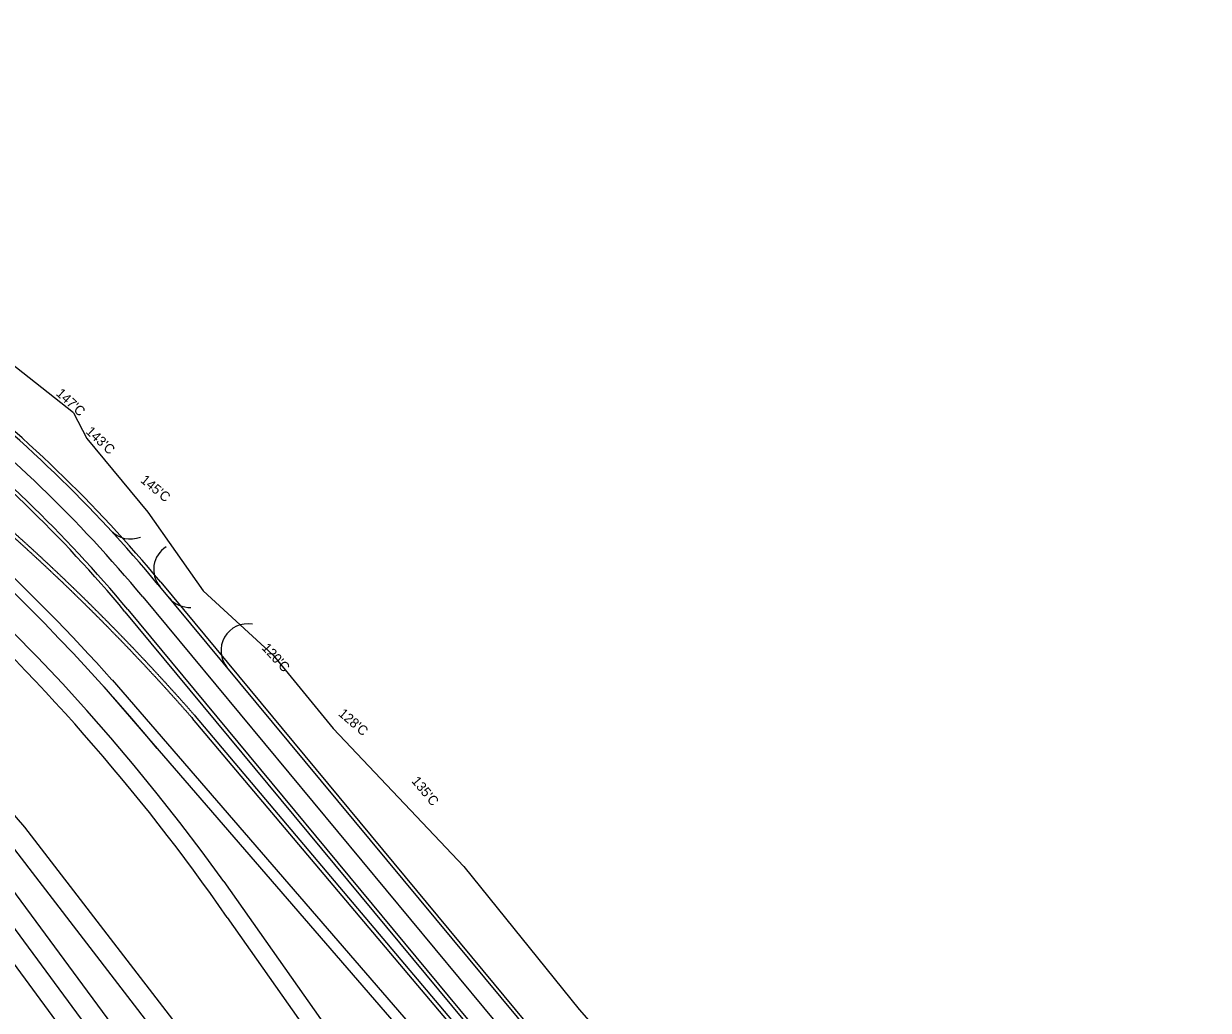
# Model space of a CAD drawing. Extents: x 1942118 to 1978871, y 789467 to 829913.
# Drawn here: x 1970305 to 1970967, y 797225 to 797777 of the extents above; entities that cross this region are included whole.
import ezdxf

# ---------------------------------------------------------------- set-up
doc = ezdxf.new("R2010")
doc.units = 0
for name, color, linetype in [('RD_PD_ALT1_CL', 7, 'Continuous'), ('RD_PD_ALT1_TrvlWay', 7, 'Continuous'), ('RD_PD_CstnLmt', 7, 'Continuous'), ('RD_PD_Driveway', 7, 'Continuous'), ('RD_PD_Final_LnLine', 7, 'Continuous'), ('RD_PD_Final_TrvlWay', 7, 'Continuous'), ('RD_PD_PaintMed', 7, 'Continuous'), ('RD_PD_PaveShd', 7, 'Continuous'), ('RD_PD_TX_CstnLmt', 7, 'Continuous'), ('RD_PD_WallFill', 7, 'Continuous')]:
    doc.layers.add(name, color=color, linetype=linetype)

msp = doc.modelspace()

# ---------------------------------------------------------------- linework, layer by layer
at = {"layer": 'RD_PD_ALT1_CL'}
msp.add_line((1970416.68, 797296.78), (1970931.78, 796566.41), dxfattribs=at)
at = {"layer": 'RD_PD_ALT1_TrvlWay'}
for radius, start, end in [(1150, 35.62905, 163.61097), (1166, 39.67545, 76.52951)]:
    msp.add_arc((1969481.96, 796626.87), radius, start, end, dxfattribs=at)
at = {"layer": 'RD_PD_CstnLmt'}
for p, q in [((1970332.67, 797559.08), (1970288.61, 797593.77)), ((1970332.67, 797559.08), (1970340.14, 797544.71)), ((1970340.14, 797544.71), (1970374.27, 797503.41)), ((1970374.27, 797503.41), (1970405.24, 797459.44)), ((1970405.24, 797459.44), (1970444.36, 797423.54)), ((1970444.36, 797423.54), (1970477.86, 797382.4)), ((1970477.86, 797382.4), (1970550.94, 797305.27)), ((1970550.94, 797305.27), (1970615.52, 797225.13)), ((1970615.52, 797225.13), (1970682.04, 797150.08))]:
    msp.add_line(p, q, dxfattribs=at)
at = {"layer": 'RD_PD_Driveway'}
for centre, start, end in [((1970364.49, 797503.48), 222.69654, 291.77483), ((1970392.48, 797471.42), 122.63026, 219.55353), ((1970397.66, 797465.18), 219.67545, 272.49926), ((1970430.13, 797426.03), 80.09893, 219.67545)]:
    msp.add_arc(centre, 15, start, end, dxfattribs=at)
at = {"layer": 'RD_PD_Final_LnLine'}
for p, q in [((1970284.69, 797310.85), (1970423.91, 797122.01)), ((1970275.06, 797303.7), (1970437.07, 797083.94)), ((1970265.4, 797296.58), (1970516.36, 796956.16))]:
    msp.add_line(p, q, dxfattribs=at)
at = {"layer": 'RD_PD_Final_TrvlWay'}
for p, q in [((1970379.89, 797463.11), (1970878.63, 796861.84)), ((1970362.95, 797449.06), (1970861.7, 796847.8)), ((1970349.66, 797405.75), (1970962.87, 796696.8)), ((1970468.57, 797095.3), (1970296.15, 797319.65))]:
    msp.add_line(p, q, dxfattribs=at)
for radius in [761, 739]:
    msp.add_arc((1969794.16, 796977.26), radius, 39.67545, 52.49072, dxfattribs=at)
at = {"layer": 'RD_PD_PaintMed'}
msp.add_line((1970371.42, 797456.09), (1970870.17, 796854.82), dxfattribs=at)
msp.add_arc((1969794.16, 796977.26), 750, 39.67545, 52.49072, dxfattribs=at)
at = {"layer": 'RD_PD_PaveShd'}
for p, q in [((1970305.44, 797327.25), (1970063.47, 797605.51)), ((1970381.42, 797464.39), (1970880.17, 796863.12)), ((1970361.41, 797447.79), (1970860.16, 796846.52)), ((1970354.19, 797409.67), (1970967.4, 796700.73)), ((1970496.9, 797078.14), (1970305.44, 797327.25)), ((1970418.57, 797276.75), (1970626.31, 796982.2))]:
    msp.add_line(p, q, dxfattribs=at)
for centre, radius, start, end in [((1969481.96, 796626.87), 1172, 41.91244, 62.0768), ((1969794.16, 796977.26), 763, 39.67545, 52.49072), ((1969794.16, 796977.26), 737, 39.67545, 52.49072), ((1969481.96, 796626.87), 1140, 34.75543, 47.7995)]:
    msp.add_arc(centre, radius, start, end, dxfattribs=at)
at = {"layer": 'RD_PD_WallFill'}
for p, q in [((1970626.99, 797118.22), (1970399.23, 797388.09)), ((1970400.74, 797389.41), (1970628.53, 797119.5))]:
    msp.add_line(p, q, dxfattribs=at)
for radius in [8428, 8430]:
    msp.add_arc((1963181.81, 792525.99), radius, 31.397656, 33.979468, dxfattribs=at)
for points in [[(1970292.6, 797498.04), (1970293.12, 797497.59), (1970293.63, 797497.13), (1970294.15, 797496.68), (1970294.66, 797496.22), (1970295.18, 797495.76), (1970295.7, 797495.3), (1970296.21, 797494.84), (1970296.73, 797494.38), (1970297.24, 797493.92), (1970297.76, 797493.47), (1970298.27, 797493.01), (1970298.78, 797492.55), (1970299.3, 797492.09), (1970299.81, 797491.62), (1970300.33, 797491.16), (1970300.84, 797490.7), (1970301.35, 797490.24), (1970301.86, 797489.78), (1970302.38, 797489.32), (1970302.89, 797488.85), (1970303.4, 797488.39), (1970303.91, 797487.93), (1970304.42, 797487.46), (1970304.93, 797487), (1970305.45, 797486.54), (1970305.96, 797486.07), (1970306.47, 797485.61), (1970306.98, 797485.14), (1970307.49, 797484.68), (1970307.99, 797484.21), (1970308.5, 797483.75), (1970309.01, 797483.28), (1970309.52, 797482.81), (1970310.03, 797482.35), (1970310.54, 797481.88), (1970311.05, 797481.41), (1970311.55, 797480.94), (1970312.06, 797480.48), (1970312.57, 797480.01), (1970313.08, 797479.54), (1970313.58, 797479.07), (1970314.09, 797478.6), (1970314.59, 797478.13), (1970315.1, 797477.66), (1970315.61, 797477.19), (1970316.11, 797476.72), (1970316.62, 797476.25), (1970317.12, 797475.78), (1970317.62, 797475.31), (1970318.13, 797474.84), (1970318.63, 797474.37), (1970319.14, 797473.89), (1970319.64, 797473.42), (1970320.14, 797472.95), (1970320.65, 797472.48), (1970321.15, 797472), (1970321.65, 797471.53), (1970322.15, 797471.05), (1970322.65, 797470.58), (1970323.16, 797470.11), (1970323.66, 797469.63), (1970324.16, 797469.16), (1970324.66, 797468.68), (1970325.16, 797468.2), (1970325.66, 797467.73), (1970326.16, 797467.25), (1970326.66, 797466.78), (1970327.16, 797466.3), (1970327.66, 797465.82), (1970328.16, 797465.34), (1970328.65, 797464.87), (1970329.15, 797464.39), (1970329.65, 797463.91), (1970330.15, 797463.43)], [(1970291.28, 797496.55), (1970291.79, 797496.09), (1970292.31, 797495.63), (1970292.82, 797495.18), (1970293.34, 797494.72), (1970293.85, 797494.26), (1970294.37, 797493.81), (1970294.88, 797493.35), (1970295.4, 797492.89), (1970295.91, 797492.43), (1970296.42, 797491.97), (1970296.94, 797491.51), (1970297.45, 797491.06), (1970297.96, 797490.6), (1970298.48, 797490.14), (1970298.99, 797489.68), (1970299.5, 797489.22), (1970300.01, 797488.75), (1970300.52, 797488.29), (1970301.04, 797487.83), (1970301.55, 797487.37), (1970302.06, 797486.91), (1970302.57, 797486.45), (1970303.08, 797485.98), (1970303.59, 797485.52), (1970304.1, 797485.06), (1970304.61, 797484.59), (1970305.12, 797484.13), (1970305.63, 797483.67), (1970306.14, 797483.2), (1970306.65, 797482.74), (1970307.15, 797482.27), (1970307.66, 797481.81), (1970308.17, 797481.34), (1970308.68, 797480.87), (1970309.18, 797480.41), (1970309.69, 797479.94), (1970310.2, 797479.47), (1970310.7, 797479.01), (1970311.21, 797478.54), (1970311.72, 797478.07), (1970312.22, 797477.6), (1970312.73, 797477.14), (1970313.23, 797476.67), (1970313.74, 797476.2), (1970314.24, 797475.73), (1970314.75, 797475.26), (1970315.25, 797474.79), (1970315.76, 797474.32), (1970316.26, 797473.85), (1970316.76, 797473.38), (1970317.27, 797472.91), (1970317.77, 797472.43), (1970318.27, 797471.96), (1970318.77, 797471.49), (1970319.27, 797471.02), (1970319.78, 797470.55), (1970320.28, 797470.07), (1970320.78, 797469.6), (1970321.28, 797469.13), (1970321.78, 797468.65), (1970322.28, 797468.18), (1970322.78, 797467.7), (1970323.28, 797467.23), (1970323.78, 797466.76), (1970324.28, 797466.28), (1970324.78, 797465.8), (1970325.28, 797465.33), (1970325.78, 797464.85), (1970326.27, 797464.38), (1970326.77, 797463.9), (1970327.27, 797463.42), (1970327.77, 797462.94), (1970328.27, 797462.47), (1970328.76, 797461.99)], [(1970328.76, 797461.99), (1970329.26, 797461.51), (1970329.75, 797461.03), (1970330.25, 797460.55), (1970330.75, 797460.07), (1970331.24, 797459.6), (1970331.74, 797459.12), (1970332.23, 797458.64), (1970332.73, 797458.16), (1970333.22, 797457.67), (1970333.72, 797457.19), (1970334.21, 797456.71), (1970334.7, 797456.23), (1970335.2, 797455.75), (1970335.69, 797455.27), (1970336.18, 797454.79), (1970336.68, 797454.3), (1970337.17, 797453.82), (1970337.66, 797453.34), (1970338.15, 797452.85), (1970338.64, 797452.37), (1970339.13, 797451.89), (1970339.63, 797451.4), (1970340.12, 797450.92), (1970340.61, 797450.43), (1970341.1, 797449.95), (1970341.59, 797449.46), (1970342.08, 797448.97), (1970342.57, 797448.49), (1970343.05, 797448), (1970343.54, 797447.52), (1970344.03, 797447.03), (1970344.52, 797446.54), (1970345.01, 797446.05), (1970345.5, 797445.57), (1970345.98, 797445.08), (1970346.47, 797444.59), (1970346.96, 797444.1), (1970347.44, 797443.61), (1970347.93, 797443.12), (1970348.42, 797442.63), (1970348.9, 797442.14), (1970349.39, 797441.65), (1970349.87, 797441.16), (1970350.36, 797440.67), (1970350.84, 797440.18), (1970351.33, 797439.69), (1970351.81, 797439.2), (1970352.29, 797438.71), (1970352.78, 797438.21), (1970353.26, 797437.72), (1970353.74, 797437.23), (1970354.23, 797436.73), (1970354.71, 797436.24), (1970355.19, 797435.75), (1970355.67, 797435.25), (1970356.15, 797434.76), (1970356.63, 797434.26), (1970357.12, 797433.77), (1970357.6, 797433.28), (1970358.08, 797432.78), (1970358.56, 797432.28), (1970359.04, 797431.79), (1970359.52, 797431.29), (1970360, 797430.8), (1970360.47, 797430.3), (1970360.95, 797429.8), (1970361.43, 797429.3), (1970361.91, 797428.81), (1970362.39, 797428.31), (1970362.87, 797427.81), (1970363.34, 797427.31), (1970363.82, 797426.81), (1970364.3, 797426.31), (1970364.77, 797425.82)], [(1970330.15, 797463.43), (1970330.65, 797462.95), (1970331.14, 797462.47), (1970331.64, 797461.99), (1970332.14, 797461.51), (1970332.63, 797461.03), (1970333.13, 797460.55), (1970333.63, 797460.07), (1970334.12, 797459.59), (1970334.62, 797459.11), (1970335.11, 797458.63), (1970335.61, 797458.15), (1970336.1, 797457.66), (1970336.59, 797457.18), (1970337.09, 797456.7), (1970337.58, 797456.21), (1970338.08, 797455.73), (1970338.57, 797455.25), (1970339.06, 797454.76), (1970339.55, 797454.28), (1970340.05, 797453.79), (1970340.54, 797453.31), (1970341.03, 797452.82), (1970341.52, 797452.34), (1970342.01, 797451.85), (1970342.5, 797451.37), (1970342.99, 797450.88), (1970343.49, 797450.39), (1970343.98, 797449.91), (1970344.47, 797449.42), (1970344.95, 797448.93), (1970345.44, 797448.44), (1970345.93, 797447.96), (1970346.42, 797447.47), (1970346.91, 797446.98), (1970347.4, 797446.49), (1970347.89, 797446), (1970348.37, 797445.51), (1970348.86, 797445.02), (1970349.35, 797444.53), (1970349.84, 797444.04), (1970350.32, 797443.55), (1970350.81, 797443.06), (1970351.29, 797442.57), (1970351.78, 797442.08), (1970352.26, 797441.58), (1970352.75, 797441.09), (1970353.23, 797440.6), (1970353.72, 797440.11), (1970354.2, 797439.61), (1970354.69, 797439.12), (1970355.17, 797438.63), (1970355.65, 797438.13), (1970356.14, 797437.64), (1970356.62, 797437.14), (1970357.1, 797436.65), (1970357.59, 797436.15), (1970358.07, 797435.66), (1970358.55, 797435.16), (1970359.03, 797434.67), (1970359.51, 797434.17), (1970359.99, 797433.68), (1970360.47, 797433.18), (1970360.95, 797432.68), (1970361.43, 797432.18), (1970361.91, 797431.69), (1970362.39, 797431.19), (1970362.87, 797430.69), (1970363.35, 797430.19), (1970363.83, 797429.69), (1970364.31, 797429.19), (1970364.79, 797428.69), (1970365.27, 797428.2), (1970365.74, 797427.7), (1970366.22, 797427.2)], [(1970364.77, 797425.81), (1970365.25, 797425.32), (1970365.73, 797424.82), (1970366.2, 797424.31), (1970366.68, 797423.81), (1970367.15, 797423.31), (1970367.63, 797422.81), (1970368.1, 797422.31), (1970368.57, 797421.81), (1970369.05, 797421.31), (1970369.52, 797420.81), (1970370, 797420.3), (1970370.47, 797419.8), (1970370.94, 797419.3), (1970371.41, 797418.79), (1970371.89, 797418.29), (1970372.36, 797417.79), (1970372.83, 797417.28), (1970373.3, 797416.78), (1970373.77, 797416.27), (1970374.24, 797415.77), (1970374.71, 797415.26), (1970375.18, 797414.76), (1970375.65, 797414.25), (1970376.12, 797413.75), (1970376.59, 797413.24), (1970377.06, 797412.73), (1970377.53, 797412.23), (1970378, 797411.72), (1970378.47, 797411.21), (1970378.94, 797410.7), (1970379.4, 797410.19), (1970379.87, 797409.69), (1970380.34, 797409.18), (1970380.8, 797408.67), (1970381.27, 797408.16), (1970381.74, 797407.65), (1970382.2, 797407.14), (1970382.67, 797406.63), (1970383.13, 797406.12), (1970383.6, 797405.61), (1970384.06, 797405.1), (1970384.53, 797404.59), (1970384.99, 797404.08), (1970385.46, 797403.56), (1970385.92, 797403.05), (1970386.38, 797402.54), (1970386.85, 797402.03), (1970387.31, 797401.52), (1970387.77, 797401), (1970388.23, 797400.49), (1970388.7, 797399.98), (1970389.16, 797399.46), (1970389.62, 797398.95), (1970390.08, 797398.43), (1970390.54, 797397.92), (1970391, 797397.4), (1970391.46, 797396.89), (1970391.92, 797396.37), (1970392.38, 797395.86), (1970392.84, 797395.34), (1970393.3, 797394.82), (1970393.76, 797394.31), (1970394.21, 797393.79), (1970394.67, 797393.27), (1970395.13, 797392.76), (1970395.59, 797392.24), (1970396.05, 797391.72), (1970396.5, 797391.2), (1970396.96, 797390.68), (1970397.42, 797390.16), (1970397.87, 797389.65), (1970398.33, 797389.12), (1970399.23, 797388.09)], [(1970366.22, 797427.19), (1970366.7, 797426.69), (1970367.17, 797426.19), (1970367.65, 797425.69), (1970368.13, 797425.19), (1970368.6, 797424.69), (1970369.08, 797424.19), (1970369.55, 797423.69), (1970370.03, 797423.18), (1970370.5, 797422.68), (1970370.98, 797422.18), (1970371.45, 797421.67), (1970371.93, 797421.17), (1970372.4, 797420.67), (1970372.87, 797420.16), (1970373.35, 797419.66), (1970373.82, 797419.15), (1970374.29, 797418.65), (1970374.76, 797418.14), (1970375.23, 797417.64), (1970375.71, 797417.13), (1970376.18, 797416.63), (1970376.65, 797416.12), (1970377.12, 797415.61), (1970377.59, 797415.11), (1970378.06, 797414.6), (1970378.53, 797414.09), (1970379, 797413.58), (1970379.47, 797413.07), (1970379.94, 797412.57), (1970380.41, 797412.06), (1970380.87, 797411.55), (1970381.34, 797411.04), (1970381.81, 797410.53), (1970382.28, 797410.02), (1970382.75, 797409.51), (1970383.21, 797409), (1970383.68, 797408.49), (1970384.15, 797407.98), (1970384.61, 797407.47), (1970385.08, 797406.96), (1970385.54, 797406.44), (1970386.01, 797405.93), (1970386.47, 797405.42), (1970386.94, 797404.91), (1970387.4, 797404.39), (1970387.87, 797403.88), (1970388.33, 797403.37), (1970388.79, 797402.85), (1970389.26, 797402.34), (1970389.72, 797401.83), (1970390.18, 797401.31), (1970390.65, 797400.8), (1970391.11, 797400.28), (1970391.57, 797399.77), (1970392.03, 797399.25), (1970392.49, 797398.74), (1970392.95, 797398.22), (1970393.41, 797397.7), (1970393.87, 797397.19), (1970394.33, 797396.67), (1970394.79, 797396.15), (1970395.25, 797395.63), (1970395.71, 797395.12), (1970396.17, 797394.6), (1970396.63, 797394.08), (1970397.09, 797393.56), (1970397.55, 797393.04), (1970398, 797392.52), (1970398.46, 797392), (1970398.92, 797391.48), (1970399.37, 797390.96), (1970399.83, 797390.44), (1970400.74, 797389.41)]]:
    msp.add_spline(points, degree=3, dxfattribs=at)

# ---------------------------------------------------------------- texts
at = {"layer": 'RD_PD_TX_CstnLmt'}
for s, rotation, p in [("147'C", 317.24991, (1970322.45, 797569.41)), ("143'C", 316.85168, (1970339.11, 797548.11)), ("145'C", 320.37875, (1970369.68, 797520.68)), ("120'C", 312.67645, (1970437.6, 797427.23)), ("128'C", 319.27833, (1970480.41, 797390.08)), ("135'C", 309.89296, (1970521.37, 797352.87))]:
    msp.add_text(s, height=5.4, rotation=rotation, dxfattribs=at).set_placement(p)

doc.saveas('drawing.dxf')
